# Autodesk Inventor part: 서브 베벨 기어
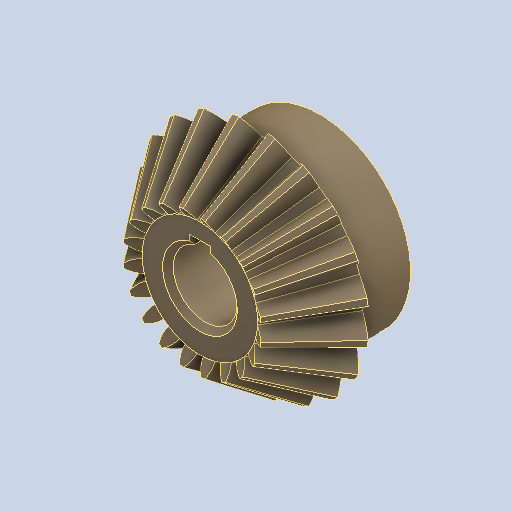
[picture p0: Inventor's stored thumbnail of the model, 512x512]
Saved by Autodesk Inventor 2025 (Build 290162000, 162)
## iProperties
Created: 2024-07
Part Number: 서브 베벨 기어
Material: 강철, 탄소
Document SubType Name: Modeling
Designer: 학생
Density: 7.87 g/cm^3
Appearance: 기본값
Author: jhkim
Revision Number: 1
Sending System: Autodesk Inventor 2025
Preprocessor: ST-DEVELOPER v20
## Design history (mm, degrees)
node "복구된 형상1"
  node "스케치11"
feature "Solid1"
node "스케치10"
node "솔리드1"
